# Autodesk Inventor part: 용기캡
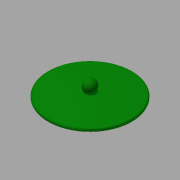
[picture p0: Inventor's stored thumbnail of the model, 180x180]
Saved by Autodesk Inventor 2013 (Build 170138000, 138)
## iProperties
Created: 2018-01
Part Number: 용기캡
Material: ABS 플라스틱
Document SubType Name: Modeling
Designer: mduedu
Density: 1 g/cm^3
Author: mduedu
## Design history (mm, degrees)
sketch "스케치1"
  geometry: L1 (-35, 2.5)-(0, 2.5); L2 (0, 5)-(0, 0); L3 (0, 0)-(-35, 0); L4 (-35, 0)-(-35, 2.5); L5 (-31, 0)-(-29, 0); L6 (-29, 0)-(-29, -2); L7 (-29, -2)-(-31, -2); L8 (-31, -2)-(-31, 0); A1 r 246.25 centre (0, -241.25) between (0, 5) and (-35, 2.5); 1 further point
  constraints: 16 end point, 4 parallel, 2 horizontal, 2 perpendicular, 2 point on circle, 1 centre point, 1 coincident, 1 midpoint, 1 point on line, 1 vertical alignment
  dimensions: "d2" = 70 diameter of L4 L2; "d3" = 5 distance from line of L2.start L3; "d4" = 2.5 distance of L3.end L1.start; "d5" = 4 distance between parallel lines of L8 L4; "d6" = 2 distance of L6.end L7.end; "d7" = 2 distance between parallel lines of L7 L3
revolve "회전1" sketch "스케치1" stored, may be unused: angle "d8" = 90 deg
chamfer "모따기1" distance "d9" = 0.5; stored, may be unused: second distance "d10" = 2, angle "d11" = 45 deg
fillet "모깎기1" dims "d12" = 1
fillet "모깎기2" dims "d13" = 1
sketch "스케치2"
  geometry: L1 (-30.5, -2)-(-31, -1.5) reference; L2 (-31, -1.5)-(-31, 0) reference; L3 (-31, 0)-(-34, 0) reference; L4 (-35, 1)-(-35, 1.632) reference; L5 (35, 1.632)-(35, 1) reference; L6 (34, 0)-(31, 0) reference; L7 (31, 0)-(31, -1.5) reference; L8 (31, -1.5)-(30.5, -2) reference; L9 (30.5, -2)-(29, -2) reference; L10 (29, -2)-(29, -1) reference; L11 (28, 0)-(-28, 0) reference; L12 (-29, -1)-(-29, -2) reference; L13 (-29, -2)-(-30.5, -2) reference; L14 (0, 14)-(0, 4); A1 r 1 centre (-34, 1) between (-35, 1) and (-34, 0) reference; A2 r 1 centre (-34, 1.632) between (-34.139, 2.622) and (-35, 1.632) reference; A3 r 246.25 centre (0, -241.25) between (34.139, 2.622) and (-34.139, 2.622) reference; A4 r 1 centre (34, 1.632) between (35, 1.632) and (34.139, 2.622) reference; A5 r 1 centre (34, 1) between (34, 0) and (35, 1) reference; A6 r 1 centre (28, -1) between (29, -1) and (28, 0) reference; A7 r 1 centre (-28, -1) between (-28, 0) and (-29, -1) reference; A8 r 5 centre (0, 9) between (0, 14) and (0, 4); 3 further points
  constraints: 2 end point, 2 midpoint, 2 point on circle, 1 centre point, 1 coincident, 1 perpendicular, 1 point on line, 1 vertical alignment
  dimensions: "d14" = 10 diameter of A8; "d16" = 9 distance of A8.centre point (0, 0)
revolve "회전2" sketch "스케치2" stored, may be unused: angle "d17" = 90 deg
fillet "모깎기3" dims "d18" = 1
node "솔리드1"
node "절단 모서리 투영1"
